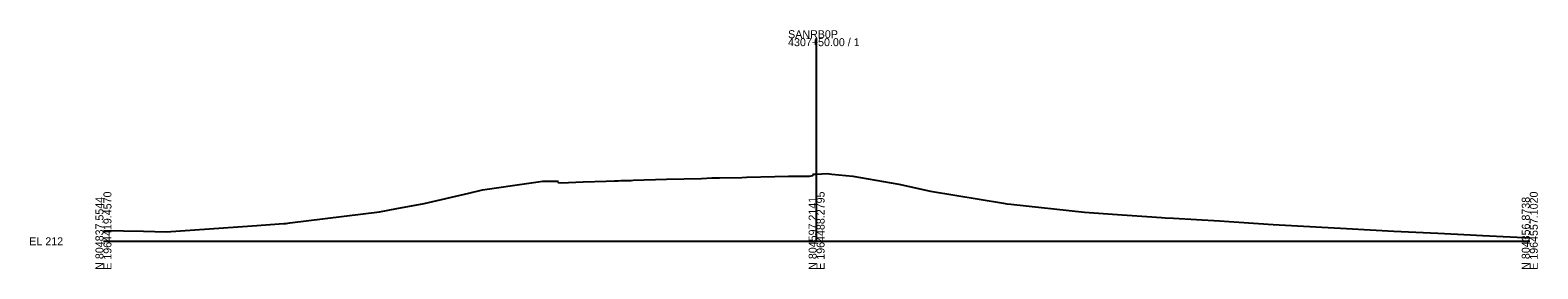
# Model space of a CAD drawing. Extents: x 1995641 to 1997170, y 790368 to 809963.
# Drawn here: x 1996641 to 1997170, y 798368 to 798452 of the extents above; entities that cross this region are included whole.
import ezdxf

# ---------------------------------------------------------------- set-up
doc = ezdxf.new("R2010")
doc.units = 0
for name, color, linetype in [('Default', 7, 'Continuous'), ('RD_GPK_XS_Cell', 7, 'Continuous'), ('RD_Sketch1', 7, 'Continuous'), ('RD_XS_ExGround', 7, 'Continuous')]:
    doc.layers.add(name, color=color, linetype=linetype)

msp = doc.modelspace()

# ---------------------------------------------------------------- linework, layer by layer
at = {"layer": 'RD_GPK_XS_Cell'}
for p, q in [((1996917.06, 798378.11), (1996917.06, 798449.44)), ((1996667.06, 798378.11), (1996917.06, 798378.11)), ((1996917.06, 798378.11), (1997167.06, 798378.11))]:
    msp.add_line(p, q, dxfattribs=at)
at = {"layer": 'RD_XS_ExGround'}
msp.add_lwpolyline([(1996667.06, 798381.9), (1996681.06, 798381.65), (1996688.99, 798381.44), (1996719.17, 798383.56), (1996730.31, 798384.32), (1996730.71, 798384.35), (1996731.13, 798384.4), (1996731.66, 798384.45), (1996732.39, 798384.55), (1996763.85, 798388.46), (1996769.92, 798389.63), (1996779.47, 798391.44), (1996795.15, 798395.06), (1996799.99, 798396.15), (1996816.16, 798398.52), (1996821.04, 798399.25), (1996823.77, 798399.24), (1996826.37, 798399.22), (1996826.48, 798398.77), (1996827.56, 798398.59), (1996835.22, 798398.98), (1996843.26, 798399.22), (1996846.24, 798399.34), (1996846.7, 798399.35), (1996847.48, 798399.36), (1996848.4, 798399.45), (1996848.72, 798399.46), (1996850.14, 798399.42), (1996851.54, 798399.49), (1996852.06, 798399.52), (1996852.81, 798399.53), (1996864.45, 798399.92), (1996876.67, 798400.21), (1996880.3, 798400.38), (1996880.73, 798400.4), (1996883.05, 798400.44), (1996890.87, 798400.56), (1996892.48, 798400.6), (1996902.46, 798400.87), (1996907.17, 798400.96), (1996914.59, 798401.04), (1996915.72, 798401.23), (1996915.83, 798401.68), (1996917.06, 798401.73), (1996920.72, 798401.89), (1996922.4, 798401.73), (1996929.79, 798400.95), (1996945.86, 798398.13), (1996956.93, 798395.73), (1996982.55, 798391.52), (1996983.79, 798391.32), (1996985.09, 798391.21), (1997011.01, 798388.33), (1997020.83, 798387.6), (1997037.97, 798386.49), (1997039.24, 798386.41), (1997042.21, 798386.24), (1997058.28, 798385.25), (1997065.09, 798384.83), (1997077.12, 798384.02), (1997092.12, 798383.19), (1997102.87, 798382.61), (1997119.41, 798381.72), (1997134.83, 798380.93), (1997146.31, 798380.34), (1997150.52, 798380.1), (1997162.61, 798379.56), (1997167.06, 798379.36)], dxfattribs=at)

# ---------------------------------------------------------------- texts
at = {"layer": 'Default'}
msp.add_text('-', height=0.0001, dxfattribs=at).set_placement((1996667.06, 798378.11))
msp.add_text('-', height=0.0001, dxfattribs=at).set_placement((1996667.06, 798378.11))
at = {"layer": 'RD_GPK_XS_Cell'}
for s, p in [('4307+50.00 / 1', (1996907.06, 798446.64)), ('SANRB0P', (1996907.06, 798449.44)), ('EL 212', (1996641.06, 798376.71))]:
    msp.add_text(s, height=2.8, dxfattribs=at).set_placement(p)
for s, p in [('N 804837.5544', (1996667.06, 798368.11)), ('E 1964419.4570', (1996669.86, 798368.11)), ('N 804597.2141', (1996917.06, 798368.11)), ('E 1964488.2795', (1996919.86, 798368.11)), ('N 804356.8738', (1997167.06, 798368.11)), ('E 1964557.1020', (1997169.86, 798368.11))]:
    msp.add_text(s, height=2.8, rotation=90, dxfattribs=at).set_placement(p)
at = {"layer": 'RD_Sketch1'}
msp.add_text('235.62', height=0.1, dxfattribs=at).set_placement((1996916.85, 798401.63))

doc.saveas('drawing.dxf')
